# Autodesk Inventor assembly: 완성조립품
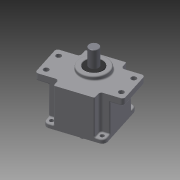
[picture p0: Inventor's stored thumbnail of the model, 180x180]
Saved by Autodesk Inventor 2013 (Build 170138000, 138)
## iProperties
Created: 2015-07
Part Number: 완성조립품
Document SubType Name: Assembly
Designer: user
Author: user
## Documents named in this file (12)
- C:\Users\user\Desktop\450734V1010\완성조립품.iam
- C:\Users\user\Desktop\450734V1010\서브축.ipt
- C:\Users\user\Desktop\450734V1010\베어링 608.ipt
- 베어링 608.ipt
- C:\Users\user\Desktop\450734V1010\베어링 6003.ipt
- 베어링 6003.ipt
- C:\Users\user\Desktop\450734V1010\메인축.ipt
- C:\Users\user\Desktop\450734V1010\본체.ipt
- C:\Users\user\Desktop\450734V1010\오일실 8x22x7.ipt
- C:\Users\user\Desktop\450734V1010\오일실 17x32x8.ipt
- C:\Users\user\Desktop\450734V1010\커버.ipt
- C:\Users\user\Desktop\450734V1010\M4x0.5x16.ipt
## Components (4 placed, 1 different names)
1. M4x0.5x12:1
2. M4x0.5x12:2
3. M4x0.5x12:3
4. M4x0.5x12:4
